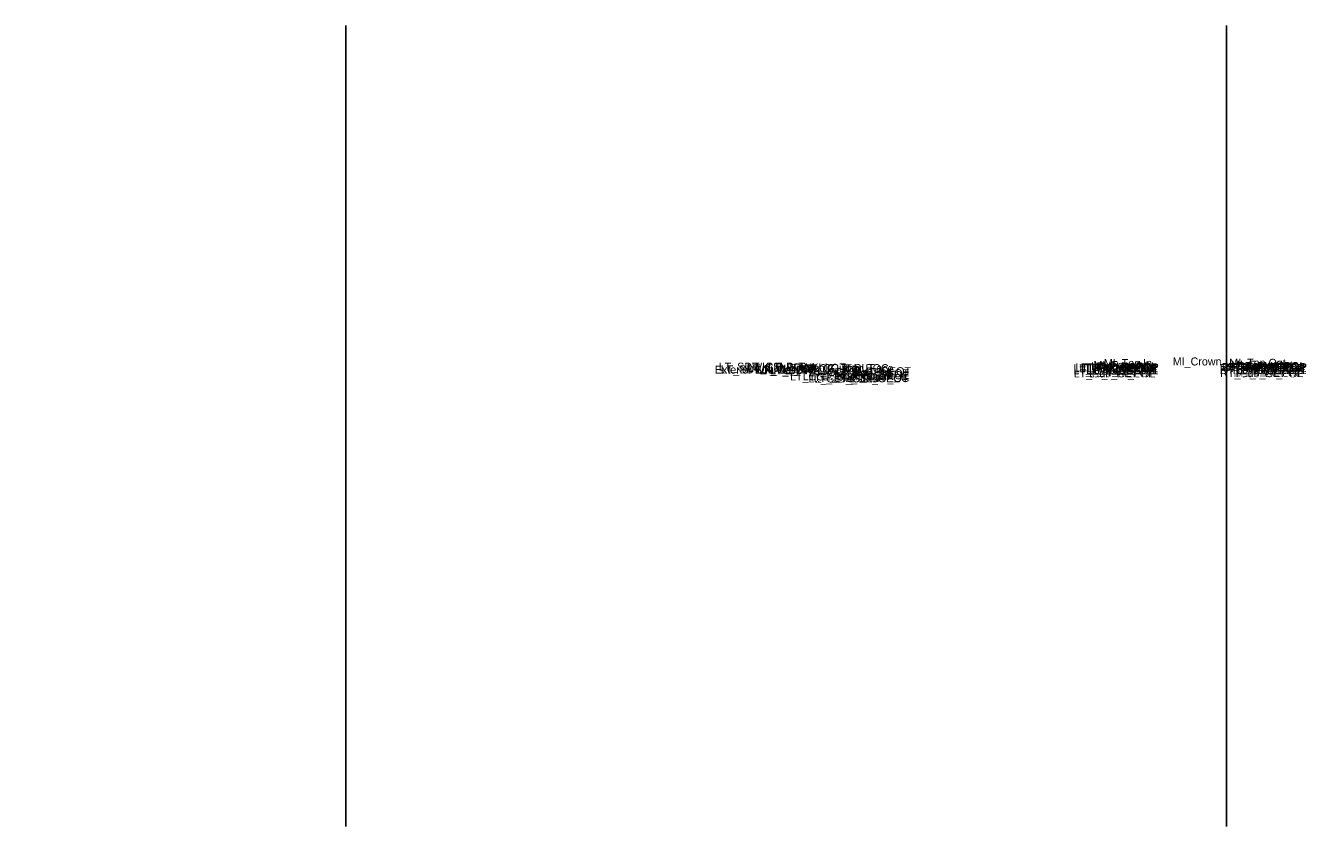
# Model space of a CAD drawing. Extents: x 0 to 6300, y -50 to 9550.
# Drawn here: x 3000 to 3160, y 7950 to 8050 of the extents above; entities that cross this region are included whole.
import ezdxf

# ---------------------------------------------------------------- set-up
doc = ezdxf.new("R2010")
doc.units = 0
for name, color, linetype in [('Default', 7, 'Continuous'), ('Prop XS Exc Vertical Line 1', 7, 'Continuous'), ('Prop XS Exc Vertical Line 2', 7, 'Continuous')]:
    doc.layers.add(name, color=color, linetype=linetype)

msp = doc.modelspace()

# ---------------------------------------------------------------- linework, layer by layer
at = {"layer": 'Prop XS Exc Vertical Line 1'}
msp.add_line((3040, 8050), (3040, 7950), dxfattribs=at)
at = {"layer": 'Prop XS Exc Vertical Line 2'}
msp.add_line((3150, 8050), (3150, 7950), dxfattribs=at)

# ---------------------------------------------------------------- texts
at = {"layer": 'Default'}
for s, height, p in [('Exterior Boundary', 1, (3086.09, 8006.54)), ('LT_SDWK_Out_Top', 1, (3086.58, 8006.91)), ('LT_SDWK_Out_Bot', 1, (3086.83, 8006.57)), ('LT_CSLP_Pnt', 1, (3090.1, 8006.91)), ('LT_Sub_Trench_Out_DLT', 1, (3090.22, 8006.76)), ('LT_Tie_Pt', 1, (3091.38, 8006.54)), ('LT_SDWK_In_Top', 1, (3092.74, 8006.81)), ('LT_SDWK_In_Bot', 1, (3092.99, 8006.47)), ('LT_CG_Top_BOC', 1, (3096.81, 8006.72)), ('LT_CG_Top_Face', 1, (3097.34, 8006.72)), ('LT_CG_Top_Gut', 1, (3097.87, 8006.22)), ('LT_PV1_OEOT', 1, (3101.23, 8006.34)), ('LT_PV2_OEEOP', 1, (3130.88, 8006.7)), ('LT_PV3_OEEOP', 1, (3130.88, 8006.45)), ('LT_PV1_OEEOP', 1, (3131.12, 8006.82)), ('LT_PV2_IEEOP', 1, (3131.64, 8006.7)), ('LT_PV1_IEEOP', 1, (3131.88, 8006.82)), ('LT_PV2_PGL1', 1, (3132.48, 8006.7)), ('LT_PV3_PGL1', 1, (3132.48, 8006.45)), ('LT_PV2_PGL', 1, (3132.86, 8006.7)), ('LT_PV1_PGL', 1, (3133.09, 8006.95)), ('MI_Face In', 1, (3133.39, 8007.11)), ('MI_Bot In', 1, (3134.56, 8006.95)), ('MI_Top In', 1, (3134.68, 8007.36)), ('MI_Crown', 1, (3143.29, 8007.56)), ('RT_PV2_OEEOP', 1, (3149.17, 8006.73)), ('RT_PV3_OEEOP', 1, (3149.17, 8006.48)), ('RT_PV1_OEEOP', 1, (3149.41, 8006.85)), ('RT_PV2_IEEOP', 1, (3149.93, 8006.73)), ('RT_PV1_IEEOP', 1, (3150.17, 8006.85)), ('MI_Top Out', 1, (3150.35, 8007.39)), ('MI_Face Out', 1, (3150.56, 8007.14)), ('RT_PV2_PGL1', 1, (3150.77, 8006.73)), ('RT_PV3_PGL1', 1, (3150.77, 8006.48)), ('RT_PV2_PGL', 1, (3151.15, 8006.73)), ('RT_PV1_PGL', 1, (3151.39, 8006.98)), ('MI_Bot Out', 1, (3151.75, 8006.98)), ('LT_CG1_Shelf_Out', 1, (3095.48, 8005.69)), ('LT_CG_Bot_BOC', 1, (3097.09, 8005.7)), ('LT_Sub_OEOP', 1, (3097.77, 8005.44)), ('LT_Sub_OEOT_CG', 1, (3098.44, 8005.5)), ('LT_PV2_OEOT', 1, (3100.99, 8006.09)), ('LT_PV3_OEOT', 1, (3100.99, 8005.84)), ('LT_Sub_OEOT', 1, (3101.04, 8005.46)), ('LT_CG_Bot_IE', 1, (3101.34, 8005.75)), ('LT_Sub_OEEOP', 1, (3130.92, 8006.07)), ('LT_PV4_PGL', 1, (3132.86, 8006.07)), ('RT_Sub_OEEOP', 1, (3149.22, 8006.1)), ('RT_PV4_PGL', 1, (3151.15, 8006.1)), ('-', 0.0001, (3000, 8000))]:
    msp.add_text(s, height=height, dxfattribs=at).set_placement(p)

doc.saveas('drawing.dxf')
